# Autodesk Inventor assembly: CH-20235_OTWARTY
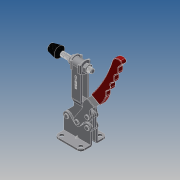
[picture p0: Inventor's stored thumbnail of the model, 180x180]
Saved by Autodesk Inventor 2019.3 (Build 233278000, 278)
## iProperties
Company: ·L?¤¤?
Created: 2010-06
Part Number: CH-20235_OTWARTY
Material: Ogólny
Description: STEP AP203
Document SubType Name: Assembly
Designer: CADENGINEERING4
Sending System: SolidWorks 2005179
Preprocessor: SwSTEP 2.0
Title: CH-20235.STEP
Author: ·L?¥Î?
Revision Number: ANY
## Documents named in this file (9)
- E:\STRONA\Horizontal toggle clamp\CH-20235\CH-20235_OTWARTY.iam
- E:\STRONA\Horizontal toggle clamp\CH-20235\20235-01___.ipt
- E:\STRONA\Horizontal toggle clamp\CH-20235\20235-05___.ipt
- E:\STRONA\Horizontal toggle clamp\CH-20235\20235-02___.ipt
- E:\STRONA\Horizontal toggle clamp\CH-20235\20235-04___.ipt
- E:\STRONA\Horizontal toggle clamp\CH-20235\FW380___.ipt
- E:\STRONA\Horizontal toggle clamp\CH-20235\38312-02___.ipt
- E:\STRONA\Horizontal toggle clamp\CH-20235\CH-FC-38312___.ipt
- E:\STRONA\Horizontal toggle clamp\CH-20235\20235-03___.ipt
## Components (14 placed, 14 different names)
1. 20235-01_??_1 — Zestawiające:13, Zestawiające:14, Zestawiające:15, Zestawiające:16, Zestawiające:21, Zestawiające:22, Zestawiające:23, Zestawiające:24, Przejściowe:1
2. 20235-05_??_2 — Zestawiające:15, Zestawiające:16
3. 20235-05_??_3 — Zestawiające:19, Zestawiające:20
4. 20235-02_??_4 — Zestawiające:7, Zestawiające:8, Kątowe:1, Zestawiające:9, Zestawiające:21, Zestawiające:22, Zestawiające:27
5. 20235-04_??_5 — Zestawiające:10, Zestawiające:11, Zestawiające:12, Zestawiające:13, Zestawiające:14, Zestawiające:17, Zestawiające:18
6. FW380_??_6 — Zestawiające:4, Zestawiające:6, Zestawiające:8, Równoległe:2, Kątowe:1
7. 38312-02_??_7 — Zestawiające:1, Zestawiające:3
8. 20235-05_??_8 — Zestawiające:23, Zestawiające:24
9. 20235-04_??_9 — Zestawiające:10, Zestawiające:11, Zestawiające:12
10. 38312-02_??_10 — Zestawiające:5, Zestawiające:6, Równoległe:1
11. CH-FC-38312_??_11 — Zestawiające:1, Zestawiające:2, Zestawiające:4, Zestawiające:5, Równoległe:1, Zestawiające:9
12. 20235-05_??_12 — Zestawiające:25, Zestawiające:26, Zestawiające:27
13. FW380_??_13 — Zestawiające:2, Zestawiające:3, Zestawiające:7, Równoległe:2
14. 20235-03_??_14 — Zestawiające:17, Zestawiające:18, Zestawiające:19, Zestawiające:20, Zestawiające:25, Zestawiające:26, Przejściowe:1
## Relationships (31: Mate 27, Flush 2, Angle 1, Transitional 1)
- Zestawiające:1 [Mate]: 38312-02_??_7 ↔ CH-FC-38312_??_11
- Zestawiające:2 [Mate]: CH-FC-38312_??_11 ↔ FW380_??_13
- Zestawiające:3 [Mate]: 38312-02_??_7 ↔ FW380_??_13
- Zestawiające:4 [Mate]: FW380_??_6 ↔ CH-FC-38312_??_11
- Zestawiające:5 [Mate]: 38312-02_??_10 ↔ CH-FC-38312_??_11
- Zestawiające:6 [Mate]: FW380_??_6 ↔ 38312-02_??_10
- Równoległe:1 [Flush]: 38312-02_??_10 ↔ CH-FC-38312_??_11
- Zestawiające:7 [Mate]: 20235-02_??_4 ↔ FW380_??_13
- Zestawiające:8 [Mate]: 20235-02_??_4 ↔ FW380_??_6
- Równoległe:2 [Flush]: FW380_??_6 ↔ FW380_??_13
- Kątowe:1 [Angle]: 20235-02_??_4 ↔ FW380_??_6
- Zestawiające:9 [Mate]: 20235-02_??_4 ↔ CH-FC-38312_??_11
- Zestawiające:10 [Mate]: 20235-04_??_5 ↔ 20235-04_??_9
- Zestawiające:11 [Mate]: 20235-04_??_5 ↔ 20235-04_??_9
- Zestawiające:12 [Mate]: 20235-04_??_5 ↔ 20235-04_??_9
- Zestawiające:13 [Mate]: 20235-01_??_1 ↔ 20235-04_??_5
- Zestawiające:14 [Mate]: 20235-01_??_1 ↔ 20235-04_??_5
- Zestawiające:15 [Mate]: 20235-01_??_1 ↔ 20235-05_??_2
- Zestawiające:16 [Mate]: 20235-01_??_1 ↔ 20235-05_??_2
- Zestawiające:17 [Mate]: 20235-04_??_5 ↔ 20235-03_??_14
- Zestawiające:18 [Mate]: 20235-04_??_5 ↔ 20235-03_??_14
- Zestawiające:19 [Mate]: 20235-05_??_3 ↔ 20235-03_??_14
- Zestawiające:20 [Mate]: 20235-05_??_3 ↔ 20235-03_??_14
- Zestawiające:21 [Mate]: 20235-01_??_1 ↔ 20235-02_??_4
- Zestawiające:22 [Mate]: 20235-01_??_1 ↔ 20235-02_??_4
- Zestawiające:23 [Mate]: 20235-01_??_1 ↔ 20235-05_??_8
- Zestawiające:24 [Mate]: 20235-01_??_1 ↔ 20235-05_??_8
- Zestawiające:25 [Mate]: 20235-05_??_12 ↔ 20235-03_??_14
- Zestawiające:26 [Mate]: 20235-05_??_12 ↔ 20235-03_??_14
- Zestawiające:27 [Mate]: 20235-02_??_4 ↔ 20235-05_??_12
- Przejściowe:1 [Transitional]: 20235-01_??_1 ↔ 20235-03_??_14
